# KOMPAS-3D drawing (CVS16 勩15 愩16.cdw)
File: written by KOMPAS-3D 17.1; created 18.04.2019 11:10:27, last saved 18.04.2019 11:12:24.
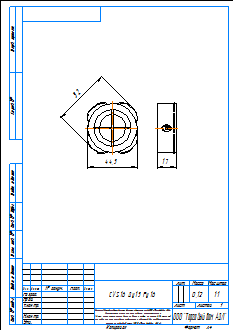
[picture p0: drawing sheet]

Sheet 1: A4, portrait

Title block, sheet 1: name: CVS16 Ду15 Ру16; material: Внимание! Данный продукт является объектом авторского права ООО «Торговый Дом АДЛ». / Запрещается изменение, копирование, распространение / (в том числе путем копирования на другие сайты и ресурсы в Интернете) / или любое иное использование информации и объектов без предварительного / согласия правообладателя (ООО «Торговый Дом АДЛ»).; mass: 0,12; sheets: 1; organisation: ООО "Торговый дом АДЛ"; sheet format: A4; stored path: \\adlc.lan\data\АДЛ_ПКД\3D-модели\ADL production\Клапаны обратные ГРАНЛОК\CVS16\KOMPAS 2D\CVS16 Ду15 Ру16.cdw

Views: Вид 1, Проекционный вид 2
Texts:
  user
Dimensions and other numbers on the sheet: 52; 44,5; 17; 1:1; 1; 0,12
